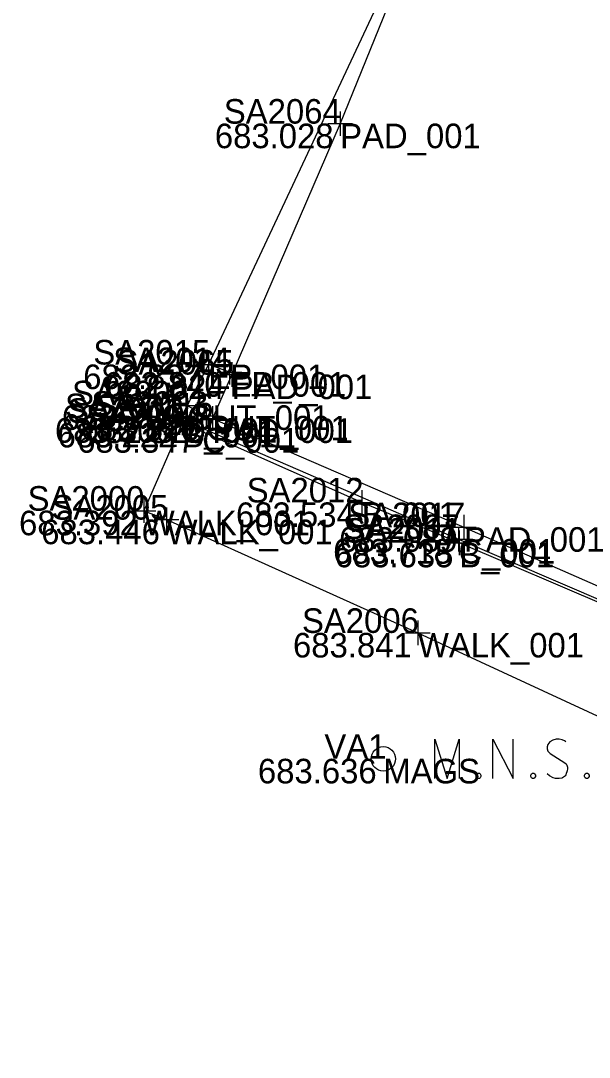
# Model space of a CAD drawing. Extents: x 1460264 to 1460899, y 578046 to 578200.
# Drawn here: x 1460264.14 to 1460287.29, y 578114.68 to 578156.88 of the extents above; entities that cross this region are included whole.
import ezdxf

# ---------------------------------------------------------------- set-up
doc = ezdxf.new("R2010")
doc.units = 0
for name, color, linetype in [('PV_X_Curb', 7, 'Continuous'), ('PV_X_EOP', 7, 'Continuous'), ('PV_X_Walk', 7, 'Continuous'), ('RD_X_Concrete_Pad', 7, 'Continuous'), ('SC_Scratch1', 7, 'Continuous'), ('SV_P_Control_Cells_Set', 7, 'Continuous'), ('SV_X_Break_Lines', 7, 'Continuous'), ('SV_X_Shot_Marker', 7, 'Continuous'), ('SV_X_Text_Comment', 7, 'Continuous'), ('SV_X_Text_Elevation', 7, 'Continuous'), ('SV_X_Text_Name', 7, 'Continuous')]:
    doc.layers.add(name, color=color, linetype=linetype)

msp = doc.modelspace()

# ---------------------------------------------------------------- linework, layer by layer
at = {"layer": 'PV_X_Curb'}
for points in [[(1460270.918, 578141.22), (1460271.694, 578140.792)], [(1460270.642, 578140.699), (1460271.537, 578140.292), (1460281.962, 578135.777), (1460294.185, 578130.516)]]:
    msp.add_lwpolyline(points, dxfattribs=at)
at = {"layer": 'PV_X_EOP'}
msp.add_lwpolyline([(1460272.643, 578142.572), (1460271.783, 578142.882)], dxfattribs=at)
at = {"layer": 'PV_X_Walk'}
msp.add_lwpolyline([(1460269.149, 578136.932), (1460270.08, 578136.568), (1460280.31, 578131.957), (1460292.326, 578126.397)], dxfattribs=at)
at = {"layer": 'RD_X_Concrete_Pad'}
msp.add_lwpolyline([(1460271.949, 578140.688), (1460282.186, 578136.261), (1460294.565, 578130.822), (1460299.791, 578142.83), (1460304.798, 578154.75), (1460309.616, 578166.714), (1460314.557, 578178.718), (1460309.827, 578180.933), (1460305.515, 578183.537), (1460301.48, 578186.635), (1460297.831, 578190.083), (1460294.382, 578194.276), (1460287.187, 578176.635), (1460282.036, 578164.729), (1460277.146, 578152.687), (1460272.732, 578142.472)], close=True, dxfattribs=at)
at = {"layer": 'SC_Scratch1'}
msp.add_lwpolyline([(1460282.036, 578164.729), (1460271.783, 578142.882), (1460270.918, 578141.22), (1460270.642, 578140.699), (1460270.714, 578140.508), (1460269.149, 578136.932), (1460270.08, 578136.568), (1460280.31, 578131.957), (1460292.326, 578126.397), (1460292.687, 578126.212), (1460293.703, 578125.829), (1460293.854, 578125.853), (1460294.741, 578125.423), (1460294.793, 578125.381), (1460308.513, 578119.82), (1460321.576, 578114.684), (1460323.488, 578118.805)], dxfattribs=at)
at = {"layer": 'SV_P_Control_Cells_Set'}
for points in [[(1460280.994, 578126.031), (1460280.994, 578127.631), (1460281.501, 578126.031), (1460281.986, 578127.631), (1460281.986, 578126.031)], [(1460280.994, 578126.031), (1460280.994, 578127.631), (1460281.501, 578126.031), (1460281.986, 578127.631), (1460281.986, 578126.031)], [(1460280.994, 578126.031), (1460280.994, 578127.631), (1460281.501, 578126.031), (1460281.986, 578127.631), (1460281.986, 578126.031)], [(1460283.364, 578126.031), (1460283.364, 578127.631), (1460284.191, 578126.031), (1460284.191, 578127.631)], [(1460283.364, 578126.031), (1460283.364, 578127.631), (1460284.191, 578126.031), (1460284.191, 578127.631)], [(1460283.364, 578126.031), (1460283.364, 578127.631), (1460284.191, 578126.031), (1460284.191, 578127.631)], [(1460286.34, 578127.518), (1460286.318, 578127.543), (1460286.285, 578127.568), (1460286.186, 578127.606), (1460286.064, 578127.631), (1460285.976, 578127.631), (1460285.943, 578127.631), (1460285.8, 578127.593), (1460285.679, 578127.518), (1460285.601, 578127.417), (1460285.579, 578127.316), (1460285.579, 578127.24), (1460285.601, 578127.14), (1460285.69, 578127.052), (1460286.296, 578126.674), (1460286.351, 578126.623), (1460286.373, 578126.573), (1460286.395, 578126.497), (1460286.395, 578126.422), (1460286.384, 578126.346), (1460286.373, 578126.296), (1460286.351, 578126.233), (1460286.329, 578126.182), (1460286.307, 578126.145), (1460286.274, 578126.107), (1460286.241, 578126.081), (1460286.197, 578126.056), (1460286.164, 578126.044), (1460286.064, 578126.031), (1460285.91, 578126.031), (1460285.811, 578126.056), (1460285.668, 578126.145), (1460285.579, 578126.22)], [(1460286.34, 578127.518), (1460286.318, 578127.543), (1460286.285, 578127.568), (1460286.186, 578127.606), (1460286.064, 578127.631), (1460285.976, 578127.631), (1460285.943, 578127.631), (1460285.8, 578127.593), (1460285.679, 578127.518), (1460285.601, 578127.417), (1460285.579, 578127.316), (1460285.579, 578127.24), (1460285.601, 578127.14), (1460285.69, 578127.052), (1460286.296, 578126.674), (1460286.351, 578126.623), (1460286.373, 578126.573), (1460286.395, 578126.497), (1460286.395, 578126.422), (1460286.384, 578126.346), (1460286.373, 578126.296), (1460286.351, 578126.233), (1460286.329, 578126.182), (1460286.307, 578126.145), (1460286.274, 578126.107), (1460286.241, 578126.081), (1460286.197, 578126.056), (1460286.164, 578126.044), (1460286.064, 578126.031), (1460285.91, 578126.031), (1460285.811, 578126.056), (1460285.668, 578126.145), (1460285.579, 578126.22)], [(1460286.34, 578127.518), (1460286.318, 578127.543), (1460286.285, 578127.568), (1460286.186, 578127.606), (1460286.064, 578127.631), (1460285.976, 578127.631), (1460285.943, 578127.631), (1460285.8, 578127.593), (1460285.679, 578127.518), (1460285.601, 578127.417), (1460285.579, 578127.316), (1460285.579, 578127.24), (1460285.601, 578127.14), (1460285.69, 578127.052), (1460286.296, 578126.674), (1460286.351, 578126.623), (1460286.373, 578126.573), (1460286.395, 578126.497), (1460286.395, 578126.422), (1460286.384, 578126.346), (1460286.373, 578126.296), (1460286.351, 578126.233), (1460286.329, 578126.182), (1460286.307, 578126.145), (1460286.274, 578126.107), (1460286.241, 578126.081), (1460286.197, 578126.056), (1460286.164, 578126.044), (1460286.064, 578126.031), (1460285.91, 578126.031), (1460285.811, 578126.056), (1460285.668, 578126.145), (1460285.579, 578126.22)], [(1460282.758, 578126.245), (1460282.813, 578126.245), (1460282.846, 578126.22), (1460282.879, 578126.17), (1460282.879, 578126.107), (1460282.846, 578126.056), (1460282.813, 578126.031), (1460282.758, 578126.031), (1460282.725, 578126.056), (1460282.692, 578126.107), (1460282.692, 578126.17), (1460282.725, 578126.22), (1460282.758, 578126.245)], [(1460282.758, 578126.245), (1460282.813, 578126.245), (1460282.846, 578126.22), (1460282.879, 578126.17), (1460282.879, 578126.107), (1460282.846, 578126.056), (1460282.813, 578126.031), (1460282.758, 578126.031), (1460282.725, 578126.056), (1460282.692, 578126.107), (1460282.692, 578126.17), (1460282.725, 578126.22), (1460282.758, 578126.245)], [(1460282.758, 578126.245), (1460282.813, 578126.245), (1460282.846, 578126.22), (1460282.879, 578126.17), (1460282.879, 578126.107), (1460282.846, 578126.056), (1460282.813, 578126.031), (1460282.758, 578126.031), (1460282.725, 578126.056), (1460282.692, 578126.107), (1460282.692, 578126.17), (1460282.725, 578126.22), (1460282.758, 578126.245)], [(1460284.973, 578126.245), (1460285.028, 578126.245), (1460285.061, 578126.22), (1460285.094, 578126.17), (1460285.094, 578126.107), (1460285.061, 578126.056), (1460285.028, 578126.031), (1460284.973, 578126.031), (1460284.94, 578126.056), (1460284.907, 578126.107), (1460284.907, 578126.17), (1460284.94, 578126.22), (1460284.973, 578126.245)], [(1460284.973, 578126.245), (1460285.028, 578126.245), (1460285.061, 578126.22), (1460285.094, 578126.17), (1460285.094, 578126.107), (1460285.061, 578126.056), (1460285.028, 578126.031), (1460284.973, 578126.031), (1460284.94, 578126.056), (1460284.907, 578126.107), (1460284.907, 578126.17), (1460284.94, 578126.22), (1460284.973, 578126.245)], [(1460284.973, 578126.245), (1460285.028, 578126.245), (1460285.061, 578126.22), (1460285.094, 578126.17), (1460285.094, 578126.107), (1460285.061, 578126.056), (1460285.028, 578126.031), (1460284.973, 578126.031), (1460284.94, 578126.056), (1460284.907, 578126.107), (1460284.907, 578126.17), (1460284.94, 578126.22), (1460284.973, 578126.245)], [(1460287.156, 578126.245), (1460287.211, 578126.245), (1460287.244, 578126.22), (1460287.277, 578126.17), (1460287.277, 578126.107), (1460287.244, 578126.056), (1460287.211, 578126.031), (1460287.156, 578126.031), (1460287.123, 578126.056), (1460287.09, 578126.107), (1460287.09, 578126.17), (1460287.123, 578126.22), (1460287.156, 578126.245)], [(1460287.156, 578126.245), (1460287.211, 578126.245), (1460287.244, 578126.22), (1460287.277, 578126.17), (1460287.277, 578126.107), (1460287.244, 578126.056), (1460287.211, 578126.031), (1460287.156, 578126.031), (1460287.123, 578126.056), (1460287.09, 578126.107), (1460287.09, 578126.17), (1460287.123, 578126.22), (1460287.156, 578126.245)], [(1460287.156, 578126.245), (1460287.211, 578126.245), (1460287.244, 578126.22), (1460287.277, 578126.17), (1460287.277, 578126.107), (1460287.244, 578126.056), (1460287.211, 578126.031), (1460287.156, 578126.031), (1460287.123, 578126.056), (1460287.09, 578126.107), (1460287.09, 578126.17), (1460287.123, 578126.22), (1460287.156, 578126.245)]]:
    msp.add_lwpolyline(points, dxfattribs=at)
msp.add_circle((1460278.904, 578126.831), 0.497, dxfattribs=at)
msp.add_circle((1460278.904, 578126.831), 0.497, dxfattribs=at)
msp.add_circle((1460278.904, 578126.831), 0.497, dxfattribs=at)
at = {"layer": 'SV_X_Break_Lines'}
msp.add_lwpolyline([(1460294.171, 578130.412), (1460281.992, 578135.628), (1460278.028, 578137.268), (1460270.714, 578140.508)], dxfattribs=at)
at = {"layer": 'SV_X_Shot_Marker'}
for p, q in [((1460277.146, 578153.187), (1460277.146, 578152.187)), ((1460276.646, 578152.687), (1460277.646, 578152.687)), ((1460277.146, 578152.687), (1460277.146, 578152.687)), ((1460271.783, 578143.382), (1460271.783, 578142.382)), ((1460271.283, 578142.882), (1460272.283, 578142.882)), ((1460271.783, 578142.882), (1460271.783, 578142.882)), ((1460272.643, 578143.072), (1460272.643, 578142.072)), ((1460272.732, 578142.972), (1460272.732, 578141.972)), ((1460272.143, 578142.572), (1460273.143, 578142.572)), ((1460272.232, 578142.472), (1460273.232, 578142.472)), ((1460272.643, 578142.572), (1460272.643, 578142.572)), ((1460272.732, 578142.472), (1460272.732, 578142.472)), ((1460270.918, 578141.72), (1460270.918, 578140.72)), ((1460270.418, 578141.22), (1460271.418, 578141.22)), ((1460270.642, 578141.199), (1460270.642, 578140.199)), ((1460270.714, 578141.008), (1460270.714, 578140.008)), ((1460270.918, 578141.22), (1460270.918, 578141.22)), ((1460271.694, 578141.292), (1460271.694, 578140.292)), ((1460271.949, 578141.188), (1460271.949, 578140.188)), ((1460270.142, 578140.699), (1460271.142, 578140.699)), ((1460270.642, 578140.699), (1460270.642, 578140.699)), ((1460271.194, 578140.792), (1460272.194, 578140.792)), ((1460271.449, 578140.688), (1460272.449, 578140.688)), ((1460271.537, 578140.792), (1460271.537, 578139.792)), ((1460271.694, 578140.792), (1460271.694, 578140.792)), ((1460271.949, 578140.688), (1460271.949, 578140.688)), ((1460270.214, 578140.508), (1460271.214, 578140.508)), ((1460270.714, 578140.508), (1460270.714, 578140.508)), ((1460271.037, 578140.292), (1460272.037, 578140.292)), ((1460271.537, 578140.292), (1460271.537, 578140.292)), ((1460278.028, 578137.768), (1460278.028, 578136.768)), ((1460269.149, 578137.432), (1460269.149, 578136.432)), ((1460277.528, 578137.268), (1460278.528, 578137.268)), ((1460278.028, 578137.268), (1460278.028, 578137.268)), ((1460268.649, 578136.932), (1460269.649, 578136.932)), ((1460269.149, 578136.932), (1460269.149, 578136.932)), ((1460270.08, 578137.068), (1460270.08, 578136.068)), ((1460269.58, 578136.568), (1460270.58, 578136.568)), ((1460270.08, 578136.568), (1460270.08, 578136.568)), ((1460282.186, 578136.761), (1460282.186, 578135.761)), ((1460281.686, 578136.261), (1460282.686, 578136.261)), ((1460281.962, 578136.277), (1460281.962, 578135.277)), ((1460281.992, 578136.128), (1460281.992, 578135.128)), ((1460282.186, 578136.261), (1460282.186, 578136.261)), ((1460281.462, 578135.777), (1460282.462, 578135.777)), ((1460281.492, 578135.628), (1460282.492, 578135.628)), ((1460281.962, 578135.777), (1460281.962, 578135.777)), ((1460281.992, 578135.628), (1460281.992, 578135.628)), ((1460280.31, 578132.457), (1460280.31, 578131.457)), ((1460279.81, 578131.957), (1460280.81, 578131.957)), ((1460280.31, 578131.957), (1460280.31, 578131.957))]:
    msp.add_line(p, q, dxfattribs=at)

# ---------------------------------------------------------------- texts
at = {"layer": 'SV_X_Text_Comment'}
for s, p in [('PAD_001', (1460277.146, 578151.687)), ('EP_001', (1460271.783, 578141.882)), ('EP_001', (1460272.643, 578141.572)), ('PAD_001', (1460272.732, 578141.472)), ('GUT_001', (1460270.918, 578140.22)), ('C_001', (1460270.642, 578139.699)), ('GUT_001', (1460271.694, 578139.792)), ('PAD_001', (1460271.949, 578139.688)), ('B_001', (1460270.714, 578139.508)), ('C_001', (1460271.537, 578139.292)), ('B_001', (1460278.028, 578136.268)), ('WALK_001', (1460269.149, 578135.932)), ('WALK_001', (1460270.08, 578135.568)), ('PAD_001', (1460282.186, 578135.261)), ('C_001', (1460281.962, 578134.777)), ('B_001', (1460281.992, 578134.628)), ('WALK_001', (1460280.31, 578130.957)), ('MAGS', (1460278.903, 578125.832)), ('MAGS', (1460278.903, 578125.832))]:
    msp.add_text(s, height=1, dxfattribs=at).set_placement(p)
at = {"layer": 'SV_X_Text_Elevation'}
for s, p in [('683.028', (1460272.046, 578151.687)), ('682.837', (1460266.687, 578141.882)), ('682.840', (1460267.53, 578141.572)), ('682.824', (1460267.61, 578141.472)), ('682.798', (1460265.818, 578140.22)), ('683.306', (1460265.538, 578139.699)), ('682.846', (1460266.59, 578139.792)), ('682.820', (1460266.835, 578139.688)), ('683.222', (1460265.641, 578139.508)), ('683.347', (1460266.441, 578139.292)), ('683.534', (1460272.906, 578136.268)), ('683.392', (1460264.076, 578135.932)), ('683.446', (1460264.976, 578135.568)), ('683.089', (1460277.102, 578135.261)), ('683.718', (1460276.861, 578134.777)), ('683.635', (1460276.922, 578134.628)), ('683.841', (1460275.228, 578130.957)), ('683.636', (1460273.799, 578125.832)), ('683.636', (1460273.799, 578125.832))]:
    msp.add_text(s, height=1, dxfattribs=at).set_placement(p)
at = {"layer": 'SV_X_Text_Name'}
for s, p in [('SA2064', (1460272.411, 578152.687)), ('SA2015', (1460267.099, 578142.882)), ('SA2014', (1460267.908, 578142.572)), ('SA2065', (1460268.048, 578142.472)), ('SA2002', (1460266.232, 578141.22)), ('SA2001', (1460265.947, 578140.699)), ('SA2013', (1460266.037, 578140.508)), ('SA2003', (1460267.017, 578140.792)), ('SA2016', (1460267.231, 578140.688)), ('SA2004', (1460266.801, 578140.292)), ('SA2012', (1460273.342, 578137.268)), ('SA2000', (1460264.423, 578136.932)), ('SA2005', (1460265.397, 578136.568)), ('SA2017', (1460277.477, 578136.261)), ('SA2007', (1460277.253, 578135.777)), ('SA2011', (1460277.297, 578135.628)), ('SA2006', (1460275.592, 578131.957)), ('VA1', (1460276.505, 578126.832)), ('VA1', (1460276.505, 578126.832))]:
    msp.add_text(s, height=1, dxfattribs=at).set_placement(p)

doc.saveas('drawing.dxf')
